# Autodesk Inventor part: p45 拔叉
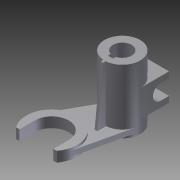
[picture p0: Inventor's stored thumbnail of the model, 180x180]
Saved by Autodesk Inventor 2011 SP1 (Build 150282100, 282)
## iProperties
Created: 2014-01
Part Number: p45 拔叉
Document SubType Name: Modeling
Designer: Administrator
Density: 1 g/cm^3
Author: Administrator
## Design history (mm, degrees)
sketch "草图1"
  geometry: C1 r 21 at (0, 0); 1 further point
  constraints: 1 centre point, 1 coincident
  dimensions: "d0" = 42 diameter of C1
extrude "拉伸1" new body sketch "草图1" distance "d1" = 75; taper "d2" = 0 deg
sketch "草图2"
  geometry: L1 (-3, -10.583)-(-3, -14); L2 (3, -10.583)-(3, -14); L3 (-3, -14)-(3, -14); C1 r 21 at (0, 0) reference; A1 r 11 centre (0, 0) between (3, -10.583) and (-3, -10.583)
  constraints: 6 end point, 2 point on circle, 1 centre point, 1 coincident, 1 parallel, 1 perpendicular, 1 vertical
  dimensions: "d3" = 22 diameter of A1; "d4" = 3 distance from line of A1.centre L1; "d5" = 6 distance between parallel lines of L1 L2; "d6" = 14 distance from line of C1.centre L3
extrude "拉伸2" cut sketch "草图2" stored distance "d7" = 75; taper "d8" = 0 deg
node "工作平面1"
sketch "草图3"
  geometry: L1 (-21, 15)-(21, 15); L2 (21, 15)-(21, 47); L3 (21, 47)-(-21, 47); L4 (-21, 47)-(-21, 15); L5 (-21, 75)-(21, 75) reference; 2 further points
  constraints: 8 end point, 2 parallel, 1 horizontal, 1 midpoint, 1 perpendicular, 1 vertical alignment
  dimensions: "d10" = 32 distance of L3.end L1.start; "d11" = 42 distance of L1.start L1.end; "d12" = 28 distance between parallel lines of L5 L3
extrude "拉伸3" join sketch "草图3" stored distance "d13" = 75; taper "d14" = 0 deg
sketch "草图4"
  geometry: L1 (21, 0)-(21, 75) reference; L2 (34, 47)-(34, 15) reference; L3 (34, 15)-(0, 15) reference; L4 (34, 47)-(0, 47) reference; L5 (11, 0)-(-10.583, 0) reference; L6 (0, 15)-(0, 47) reference; L7 (24, 22)-(34, 22); L8 (24, 40)-(34, 40); A1 r 9 centre (24, 31) between (24, 40) and (24, 22); 1 further point
  constraints: 4 end point, 2 perpendicular, 2 point on circle, 2 point on line, 2 tangent, 1 centre point
  dimensions: "d15" = 18 diameter of A1; "d16" = 24 distance from line of L6 A1.centre
extrude "拉伸4" cut sketch "草图4" stored distance "d17" = 75; taper "d18" = 0 deg
sketch "草图5"
  geometry: L1 (-3, -60)-(-3, -78); L2 (-43, -60)-(-43, -78); L3 (1, -78)-(-3, -78); L4 (-43, -78)-(-47, -78); C1 r 21 at (0, 0) reference; A1 r 30 centre (-23, -60) between (1, -78) and (-47, -78); A2 r 20 centre (-23, -60) between (-3, -60) and (-43, -60); 1 further point
  constraints: 8 end point, 4 perpendicular, 4 point on circle, 2 centre point, 2 horizontal, 2 tangent, 1 coincident
  dimensions: "d19" = 60 diameter of A1; "d21" = 60 vertical distance of point (0, 0) A1.centre; "d22" = 40 diameter of A2; "d37" = 23 horizontal distance of point (0, 0) A1.centre
extrude "拉伸5" join sketch "草图5" distance "d24" = 12; taper "d25" = 0 deg
node "工作平面2"
sketch "草图6"
  geometry: L1 (-6.24, -66.709)-(-20.468, -4.696); L2 (49.232, -45.444)-(18.363, 10.189); A1 r 30 centre (23, -60) between (47, -78) and (-1, -78) reference; A2 r 21 centre (0, 0) between (-20.468, -4.696) and (18.363, 10.189) reference; 1 further point
  constraints: 4 end point, 4 point on circle, 4 tangent
extrude "拉伸6" join sketch "草图6" stored distance "d27" = 6; taper "d28" = 0 deg
sketch "草图7"
  geometry: L1 (-4.696, 9)-(-66.709, 9) reference; L2 (-21, 0)-(-21, 75) reference; L3 (-21, 75)-(21, 75) reference; L4 (-21, 75)-(-24, 75); L5 (-24, 75)-(-31, 9); 1 further point
  constraints: 4 end point, 2 point on line, 1 collinear
  dimensions: "d30" = 10 distance from line of L2 L5.end; "d31" = 3 distance of L4.start L4.end
feature "加强筋1" sketch "草图7" dims "d32" = 1, "d33" = 3, "d34" = 0
fillet "圆角1" dims "d35" = 0.5
fillet "圆角2" dims "d36" = 0.5
node "实体1"
other parameters: "d9" = 34, "d23" = 18, "d26" = -6
